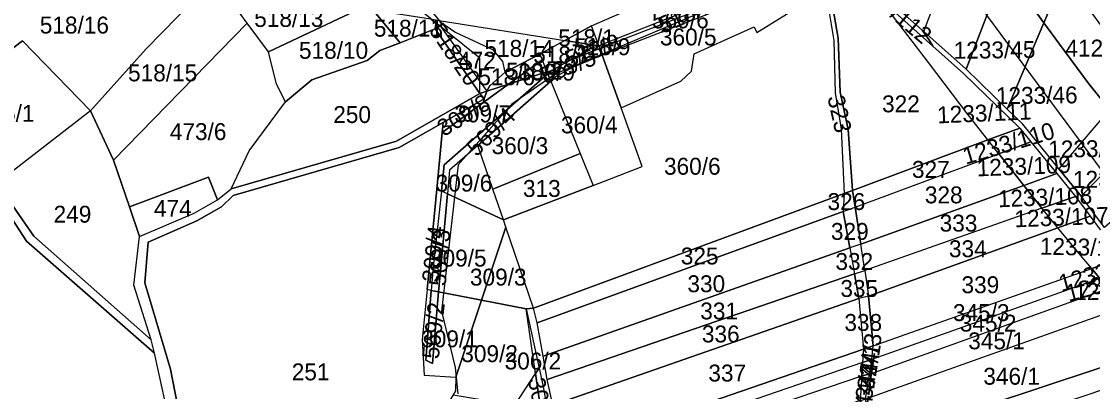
# Model space of a CAD drawing. Extents: x -623250 to -619626, y -1079612 to -1075424.
# Drawn here: x -621523 to -620889, y -1076399 to -1076180 of the extents above; entities that cross this region are included whole.
import ezdxf

# ---------------------------------------------------------------- set-up
doc = ezdxf.new("R2010")
doc.units = 0
for name, color, linetype in [('Cestní síť', 7, 'Continuous'), ('Dálnice a přivaděč', 7, 'Continuous'), ('Hranice převzatá (k_ú_Džbánov - vnitřní obvod)', 7, 'Continuous'), ('Hranice šetřená (k_ú_Džbánov - vnitřní obvod)', 7, 'Continuous'), ('Parcela nároku', 7, 'Continuous'), ('Parcelní číslo', 7, 'Continuous'), ('Vodní toky', 7, 'Continuous')]:
    doc.layers.add(name, color=color, linetype=linetype)

msp = doc.modelspace()

# ---------------------------------------------------------------- linework, layer by layer
at = {"layer": 'Cestní síť'}
for p, q in [((-621251.46, -1076201.51), (-621289.81, -1076170.77)), ((-621251.46, -1076222.32), (-621251.46, -1076201.51))]:
    msp.add_line(p, q, dxfattribs=at)
at = {"layer": 'Dálnice a přivaděč'}
msp.add_lwpolyline([(-621211.3, -1075762.42), (-621042.48, -1076053.84), (-620715.11, -1076495.7), (-620421.91, -1076809.46), (-620180.94, -1077181.74)], dxfattribs=at)
at = {"layer": 'Hranice převzatá (k_ú_Džbánov - vnitřní obvod)'}
msp.add_line((-621579.54, -1076234.75), (-621521.93, -1076191.24), dxfattribs=at)
at = {"layer": 'Hranice šetřená (k_ú_Džbánov - vnitřní obvod)'}
msp.add_line((-621521.93, -1076191.24), (-621481.81, -1076232.64), dxfattribs=at)
for points in [[(-621398.6, -1076278.8), (-621387.93, -1076256.33), (-621366.5, -1076227.36), (-621350.88, -1076214.35), (-621318.15, -1076202.75), (-621310.65, -1076196.95), (-621298.69, -1076192.28), (-621277.92, -1076184.17), (-621251.46, -1076222.32), (-621248.98, -1076225.48)], [(-621248.98, -1076225.48), (-621273.17, -1076239.48), (-621273.74, -1076245.43), (-621276.97, -1076278.86), (-621282.72, -1076338.34), (-621285.57, -1076367.86), (-621284.5, -1076389.01), (-621265.66, -1076390.24), (-621265.87, -1076398.19), (-621267.29, -1076400.57), (-621287.59, -1076434.78)], [(-621481.81, -1076232.64), (-621468.08, -1076261.86), (-621458.77, -1076289.32), (-621452.8, -1076306.94)], [(-621452.8, -1076306.94), (-621420.38, -1076293.14), (-621406.58, -1076285.18), (-621398.6, -1076278.8)]]:
    msp.add_lwpolyline(points, dxfattribs=at)
at = {"layer": 'Parcela nároku'}
for points in [[(-621115.64, -1076136.14), (-621117.67, -1076134.09), (-621106.64, -1076105.12), (-621112.1, -1076099.11), (-621115.06, -1076094.93), (-621125.96, -1076121.85), (-621133.54, -1076112.69), (-621138.97, -1076106.12), (-621291.08, -1076154.04), (-621287.17, -1076164.84), (-621275.63, -1076179.09), (-621201.26, -1076190.91), (-621185.47, -1076182.33), (-621164.23, -1076173.07), (-621116.59, -1076154.34)], [(-621608.24, -1076210.58), (-621629.35, -1076180.25), (-621633.46, -1076172.64), (-621671.01, -1076103.12), (-621673.69, -1076105.55), (-621673.97, -1076108.64), (-621630.46, -1076185.6), (-621609.84, -1076214.68), (-621593.16, -1076232.82), (-621559.82, -1076255.99), (-621548.19, -1076267.39), (-621534.67, -1076286.18), (-621519.6, -1076309.69), (-621443.92, -1076376.02), (-621445.95, -1076368.04), (-621515.23, -1076306.72), (-621537.06, -1076275.42), (-621545.36, -1076263.71), (-621552.94, -1076255.31), (-621556.59, -1076252.07), (-621565.07, -1076245.21), (-621579.54, -1076234.75), (-621591.29, -1076229.48)], [(-620981.03, -1076125.68), (-621000.13, -1076175.93), (-620990.09, -1076184.83), (-620989.05, -1076185.75), (-620962.72, -1076115.61), (-620972.17, -1076100.76)], [(-620962.72, -1076115.61), (-620945.72, -1076141.84), (-620941.1, -1076148.36), (-620964.04, -1076207.93), (-620989.05, -1076185.75)], [(-621116.59, -1076154.34), (-621115.64, -1076136.14), (-621088.15, -1076132.5), (-621088.62, -1076135.84), (-621091.79, -1076143.34), (-621096.62, -1076149.38), (-621100.38, -1076152.42), (-621105.1, -1076155), (-621103.02, -1076163.08), (-621181.25, -1076194.09), (-621185.47, -1076182.33), (-621164.23, -1076173.07)], [(-620983.64, -1076194.27), (-620986.12, -1076190.38), (-620990.09, -1076184.83), (-621000.13, -1076175.93), (-621010.03, -1076167.16), (-621020.59, -1076157.79), (-621025.94, -1076153.05), (-621029.28, -1076149.52), (-621045.76, -1076132.11), (-621046.36, -1076134.95), (-621043.64, -1076137.84), (-621036.2, -1076145.74), (-621027.6, -1076154.87), (-621015.19, -1076165.99)], [(-621545.21, -1076174.84), (-621511.86, -1076137.39), (-621411.38, -1076157.52), (-621448.91, -1076195.83), (-621481.81, -1076232.64), (-621521.93, -1076191.24), (-621579.54, -1076234.75), (-621591.29, -1076229.48), (-621571.76, -1076206.32)], [(-621184.57, -1076276.71), (-621155.58, -1076265.61), (-621168.04, -1076230.88), (-621132.79, -1076214.96), (-621126.36, -1076209.09), (-621124.87, -1076198.94), (-621089.4, -1076182.83), (-621087.81, -1076186.18), (-621063.52, -1076171.28), (-621067.09, -1076159.01), (-621062.29, -1076156.68), (-621053.44, -1076148.59), (-621047.26, -1076139.56), (-621046.46, -1076140.01), (-621046.9, -1076162.42), (-621042.18, -1076191.09), (-621041.44, -1076221.89), (-621037.97, -1076243.36), (-621036.14, -1076281.57), (-621219.72, -1076349.42), (-621236.11, -1076301.49), (-621237.65, -1076297.02)], [(-621043.75, -1076141.52), (-621046.46, -1076140.01), (-621046.9, -1076162.42), (-621042.18, -1076191.09), (-621041.44, -1076221.89), (-621037.97, -1076243.36), (-621036.14, -1076281.57), (-621031.17, -1076279.7), (-621033.73, -1076243.61), (-621038.59, -1076221.47), (-621039.62, -1076189.6), (-621044.35, -1076162.21)], [(-620951.18, -1076249.84), (-620962.76, -1076235.06), (-620986.33, -1076204.09), (-621015.19, -1076165.99), (-621027.6, -1076154.87), (-621036.2, -1076145.74), (-621043.75, -1076141.52), (-621044.35, -1076162.21), (-621039.62, -1076189.6), (-621038.59, -1076221.47), (-621033.73, -1076243.61), (-621031.17, -1076279.7)], [(-620936.62, -1076136.73), (-620906.01, -1076152.15), (-620918.03, -1076180.48), (-620928.01, -1076166.82), (-620941.1, -1076148.36)], [(-620964.04, -1076207.93), (-620941.1, -1076148.36), (-620928.01, -1076166.82), (-620918.03, -1076180.48), (-620939.7, -1076231.54)], [(-620906.01, -1076152.15), (-620862.49, -1076212.3), (-620879.21, -1076231.86), (-620891.48, -1076216.57), (-620908.73, -1076193.21), (-620918.03, -1076180.48)], [(-621389.09, -1076180.71), (-621392.88, -1076175.55), (-621405.44, -1076158.46), (-621411.38, -1076157.52), (-621448.91, -1076195.83), (-621481.81, -1076232.64), (-621468.08, -1076261.86)], [(-621384.78, -1076161.74), (-621321.63, -1076171.78), (-621376.56, -1076197.76), (-621389.09, -1076180.71), (-621392.88, -1076175.55)], [(-621100.8, -1076169.23), (-621179.22, -1076199.74), (-621168.04, -1076230.88), (-621132.79, -1076214.96), (-621126.36, -1076209.09), (-621124.87, -1076198.94), (-621089.4, -1076182.83), (-621087.81, -1076186.18), (-621063.52, -1076171.28), (-621067.09, -1076159.01), (-621086.5, -1076168.47), (-621097.9, -1076174.53)], [(-621102.49, -1076165.14), (-621103.02, -1076163.08), (-621181.25, -1076194.09), (-621177.95, -1076194.61)], [(-621180.68, -1076195.68), (-621177.95, -1076194.61), (-621102.49, -1076165.14), (-621100.8, -1076169.23), (-621179.22, -1076199.74)], [(-620983.64, -1076194.27), (-620965.61, -1076210.43), (-620932.35, -1076242.81), (-620951.18, -1076249.84), (-620962.76, -1076235.06), (-620986.33, -1076204.09), (-621015.19, -1076165.99)], [(-621314.75, -1076172.87), (-621298.69, -1076192.28), (-621310.65, -1076196.95), (-621318.15, -1076202.75), (-621350.88, -1076214.35), (-621366.5, -1076227.36), (-621371.7, -1076216.84), (-621376.56, -1076197.76), (-621321.63, -1076171.78)], [(-621314.75, -1076172.87), (-621280.8, -1076178.27), (-621277.59, -1076181.22), (-621277.92, -1076184.17), (-621298.69, -1076192.28)], [(-621376.56, -1076197.76), (-621389.09, -1076180.71), (-621468.08, -1076261.86), (-621458.77, -1076289.32), (-621412.06, -1076271.81), (-621406.58, -1076285.18), (-621398.6, -1076278.8), (-621387.93, -1076256.33), (-621366.5, -1076227.36), (-621371.7, -1076216.84)], [(-621274.68, -1076180.26), (-621274.5, -1076183.18), (-621247.35, -1076220.98), (-621251.46, -1076222.32), (-621277.92, -1076184.17), (-621277.59, -1076181.22), (-621280.8, -1076178.27), (-621275.63, -1076179.09)], [(-621275.63, -1076179.09), (-621201.26, -1076190.91), (-621216.16, -1076199.01), (-621236.49, -1076209.65), (-621237.87, -1076203.47), (-621243.4, -1076196.62), (-621266.41, -1076186.05), (-621274.68, -1076180.26)], [(-621236.49, -1076209.65), (-621237.87, -1076203.47), (-621243.4, -1076196.62), (-621266.41, -1076186.05), (-621274.68, -1076180.26), (-621274.5, -1076183.18), (-621247.35, -1076220.98), (-621245.49, -1076217.63)], [(-620918.03, -1076180.48), (-620908.73, -1076193.21), (-620891.48, -1076216.57), (-620879.21, -1076231.86), (-620909.12, -1076266.84), (-620930.47, -1076240.49), (-620939.7, -1076231.54)], [(-621398.6, -1076278.8), (-621387.93, -1076256.33), (-621366.5, -1076227.36), (-621350.88, -1076214.35), (-621318.15, -1076202.75), (-621310.65, -1076196.95), (-621298.69, -1076192.28), (-621277.92, -1076184.17), (-621251.46, -1076222.32), (-621300.88, -1076250.62)], [(-621181.25, -1076194.09), (-621185.47, -1076182.33), (-621201.26, -1076190.91)], [(-621579.54, -1076234.75), (-621521.93, -1076191.24), (-621481.81, -1076232.64), (-621537.06, -1076275.42), (-621545.36, -1076263.71), (-621552.94, -1076255.31), (-621556.59, -1076252.07), (-621565.07, -1076245.21)], [(-621201.26, -1076190.91), (-621216.16, -1076199.01), (-621214.79, -1076202.37), (-621211.9, -1076209.47), (-621208.78, -1076208.46), (-621198.57, -1076202.83), (-621186.07, -1076195.62), (-621181.25, -1076194.09)], [(-621247.35, -1076220.98), (-621245.49, -1076217.63), (-621236.49, -1076209.65), (-621216.16, -1076199.01), (-621214.79, -1076202.37), (-621234.61, -1076216.84)], [(-621185.32, -1076197.49), (-621180.68, -1076195.68), (-621179.22, -1076199.74), (-621183.92, -1076201.57), (-621196.4, -1076206.77), (-621206.39, -1076212.29), (-621209.61, -1076215.12), (-621211.38, -1076210.75), (-621208.78, -1076208.46), (-621198.57, -1076202.83)], [(-621155.58, -1076265.61), (-621168.04, -1076230.88), (-621179.22, -1076199.74), (-621183.92, -1076201.57), (-621196.4, -1076206.77), (-621206.39, -1076212.29), (-621209.61, -1076215.12), (-621192.25, -1076257.82), (-621184.57, -1076276.71)], [(-621198.57, -1076202.83), (-621186.07, -1076195.62), (-621181.25, -1076194.09), (-621180.68, -1076195.68), (-621185.32, -1076197.49)], [(-621181.25, -1076194.09), (-621177.95, -1076194.61), (-621180.68, -1076195.68)], [(-621214.79, -1076202.37), (-621211.9, -1076209.47), (-621234.61, -1076216.84)], [(-621273.74, -1076245.43), (-621234.61, -1076216.84), (-621211.9, -1076209.47), (-621211.38, -1076210.75), (-621272.57, -1076264.53), (-621274.27, -1076280.11), (-621276.97, -1076278.86)], [(-621272.57, -1076264.53), (-621211.38, -1076210.75), (-621209.61, -1076215.12), (-621252.79, -1076253.14), (-621269.4, -1076267.61), (-621270.69, -1076281.77), (-621274.27, -1076280.11)], [(-621211.9, -1076209.47), (-621208.78, -1076208.46), (-621211.38, -1076210.75)], [(-621248.98, -1076225.48), (-621247.35, -1076220.98), (-621234.61, -1076216.84), (-621273.74, -1076245.43), (-621273.17, -1076239.48)], [(-621252.79, -1076253.14), (-621209.61, -1076215.12), (-621192.25, -1076257.82), (-621243.87, -1076278.99)], [(-621468.08, -1076261.86), (-621481.81, -1076232.64), (-621537.06, -1076275.42), (-621515.23, -1076306.72), (-621445.95, -1076368.04), (-621456.14, -1076335.71), (-621452.8, -1076306.94), (-621458.77, -1076289.32)], [(-620879.21, -1076231.86), (-620909.12, -1076266.84), (-620896, -1076283.02), (-620863.74, -1076249.9), (-620872.76, -1076239.91)], [(-620932.35, -1076242.81), (-620925.69, -1076251), (-620944.74, -1076258.07), (-620951.18, -1076249.84)], [(-620944.74, -1076258.07), (-620951.18, -1076249.84), (-621031.17, -1076279.7), (-621029.68, -1076289.57)], [(-620863.74, -1076249.9), (-620855.36, -1076259.18), (-620845.7, -1076268.87), (-620879.11, -1076298.89), (-620882.2, -1076301.66), (-620896, -1076283.02)], [(-621243.87, -1076278.99), (-621252.79, -1076253.14), (-621269.4, -1076267.61), (-621270.69, -1076281.77), (-621237.65, -1076297.02)], [(-620944.74, -1076258.07), (-620925.69, -1076251), (-620910.45, -1076269.73), (-620929.96, -1076276.75), (-620936.5, -1076268.58)], [(-621243.87, -1076278.99), (-621192.25, -1076257.82), (-621184.57, -1076276.71), (-621237.65, -1076297.02)], [(-621029.68, -1076289.57), (-620944.74, -1076258.07), (-620936.5, -1076268.58), (-620929.96, -1076276.75), (-621026.37, -1076311.45)], [(-621406.58, -1076285.18), (-621412.06, -1076271.81), (-621458.77, -1076289.32), (-621452.8, -1076306.94), (-621420.38, -1076293.14)], [(-620929.96, -1076276.75), (-620910.45, -1076269.73), (-620899.46, -1076283.25), (-620919.19, -1076290.18)], [(-621282.72, -1076338.34), (-621276.97, -1076278.86), (-621274.27, -1076280.11), (-621279.16, -1076324.82), (-621280.24, -1076338.82)], [(-621270.69, -1076281.77), (-621274.27, -1076280.11), (-621279.16, -1076324.82), (-621280.24, -1076338.82), (-621275.9, -1076339.67), (-621274.64, -1076325.25)], [(-621274.64, -1076325.25), (-621275.9, -1076339.67), (-621250.47, -1076344.63), (-621236.11, -1076301.49), (-621237.65, -1076297.02), (-621270.69, -1076281.77)], [(-621219.72, -1076349.42), (-621036.14, -1076281.57), (-621036.71, -1076292.18), (-621217.58, -1076357.97)], [(-621036.14, -1076281.57), (-621036.71, -1076292.18), (-621029.68, -1076289.57), (-621031.17, -1076279.7)], [(-621026.37, -1076311.45), (-620929.96, -1076276.75), (-620919.19, -1076290.18), (-621024.01, -1076327.01)], [(-620899.46, -1076283.25), (-620890.78, -1076294.93), (-620909.76, -1076301.79), (-620913.91, -1076296.76), (-620919.19, -1076290.18)], [(-621217.58, -1076357.97), (-621036.71, -1076292.18), (-621032.84, -1076313.74), (-621214.08, -1076377.82)], [(-621036.71, -1076292.18), (-621029.68, -1076289.57), (-621026.37, -1076311.45), (-621032.84, -1076313.74)], [(-620909.76, -1076301.79), (-620913.91, -1076296.76), (-620919.19, -1076290.18), (-621024.01, -1076327.01), (-621021.7, -1076342.29)], [(-620884.55, -1076303.3), (-620873.36, -1076320.14), (-620889.79, -1076325.94), (-620894.38, -1076320.42), (-620909.76, -1076301.79), (-620890.78, -1076294.93)], [(-621219.72, -1076349.42), (-621236.11, -1076301.49), (-621250.47, -1076344.63), (-621224.07, -1076349.79)], [(-620894.38, -1076320.42), (-620909.76, -1076301.79), (-621021.7, -1076342.29), (-621019.01, -1076371.58), (-620889.79, -1076325.94)], [(-621032.84, -1076313.74), (-621030.08, -1076329.13), (-621211.65, -1076391.56), (-621214.08, -1076377.82)], [(-621024.01, -1076327.01), (-621026.37, -1076311.45), (-621032.84, -1076313.74), (-621030.08, -1076329.13)], [(-621019.78, -1076379.78), (-621019.01, -1076371.58), (-620889.79, -1076325.94), (-620884.98, -1076331.71)], [(-620889.79, -1076325.94), (-620873.36, -1076320.14), (-620868.82, -1076325.95), (-620884.98, -1076331.71)], [(-621030.08, -1076329.13), (-621027.46, -1076343.71), (-621208.34, -1076406.79), (-621211.65, -1076391.56)], [(-621030.08, -1076329.13), (-621024.01, -1076327.01), (-621021.7, -1076342.29), (-621027.46, -1076343.71)], [(-620879.98, -1076337.73), (-620884.98, -1076331.71), (-621019.78, -1076379.78), (-621020.46, -1076384.11), (-621021.13, -1076388.31)], [(-621250.47, -1076344.63), (-621275.9, -1076339.67), (-621279.61, -1076382.04), (-621283.44, -1076380.1), (-621280.24, -1076338.82), (-621282.72, -1076338.34), (-621285.57, -1076367.86), (-621284.5, -1076389.01), (-621265.66, -1076390.24)], [(-621275.9, -1076339.67), (-621280.24, -1076338.82), (-621283.44, -1076380.1), (-621279.61, -1076382.04)], [(-621021.13, -1076388.31), (-620879.98, -1076337.73), (-620870.74, -1076348.82), (-621023.49, -1076403.2)], [(-621224.07, -1076349.79), (-621250.47, -1076344.63), (-621265.66, -1076390.24), (-621265.87, -1076398.19), (-621267.29, -1076400.57), (-621230.78, -1076406.79), (-621218.56, -1076387.98)], [(-621208.34, -1076406.79), (-621027.46, -1076343.71), (-621024.8, -1076373.62), (-621199.34, -1076433.72), (-621204.93, -1076422.43)], [(-621019.01, -1076371.58), (-621021.7, -1076342.29), (-621027.46, -1076343.71), (-621024.8, -1076373.62)], [(-621208.34, -1076406.79), (-621211.65, -1076391.56), (-621214.08, -1076377.82), (-621217.58, -1076357.97), (-621219.72, -1076349.42), (-621224.07, -1076349.79), (-621216.51, -1076384.81), (-621214.33, -1076394.9), (-621209.35, -1076420.98), (-621154.18, -1076534.12), (-621073.3, -1076707.13), (-621070.3, -1076705.45), (-621118.59, -1076599.86), (-621139.26, -1076556.24), (-621151.08, -1076531.28), (-621162.18, -1076508.84), (-621168.39, -1076496.29), (-621174.76, -1076483.41), (-621186.59, -1076459.5), (-621193.11, -1076446.32), (-621196.12, -1076440.23), (-621199.34, -1076433.72), (-621204.93, -1076422.43)], [(-621224.07, -1076349.79), (-621216.51, -1076384.81), (-621218.56, -1076387.98)], [(-620856.46, -1076365.89), (-620870.74, -1076348.82), (-621023.49, -1076403.2), (-621021.51, -1076429.95), (-620850.81, -1076373.39)], [(-621199.34, -1076433.72), (-621024.8, -1076373.62), (-621025.39, -1076381.44), (-621196.12, -1076440.23)], [(-621024.8, -1076373.62), (-621025.39, -1076381.44), (-621019.78, -1076379.78), (-621019.01, -1076371.58)], [(-620845.66, -1076381.41), (-620850.81, -1076373.39), (-621021.51, -1076429.95), (-621020.47, -1076443.97), (-620844.2, -1076384.27)], [(-621025.39, -1076381.44), (-621196.12, -1076440.23), (-621193.11, -1076446.32), (-621025.72, -1076389.45)], [(-621025.39, -1076381.44), (-621025.72, -1076389.45), (-621021.13, -1076388.31), (-621020.46, -1076384.11), (-621019.78, -1076379.78)], [(-621230.78, -1076406.79), (-621218.56, -1076387.98), (-621213.66, -1076421.95), (-621209.35, -1076420.98), (-621154.18, -1076534.12), (-621073.3, -1076707.13), (-621076.55, -1076708.96), (-621098.91, -1076722.13), (-621152.55, -1076609.83), (-621197.51, -1076520.1), (-621242.51, -1076430.2), (-621244, -1076427.14)], [(-621214.33, -1076394.9), (-621209.35, -1076420.98), (-621213.66, -1076421.95), (-621218.56, -1076387.98), (-621216.51, -1076384.81)], [(-621193.11, -1076446.32), (-621025.72, -1076389.45), (-621026.74, -1076403.96), (-621186.59, -1076459.5)], [(-621021.13, -1076388.31), (-621025.72, -1076389.45), (-621026.74, -1076403.96), (-621023.49, -1076403.2)]]:
    msp.add_lwpolyline(points, close=True, dxfattribs=at)
for points in [[(-621433.49, -1076423.69), (-621443.92, -1076376.02), (-621519.6, -1076309.69), (-621534.67, -1076286.18), (-621548.19, -1076267.39), (-621559.82, -1076255.99), (-621593.16, -1076232.82), (-621609.84, -1076214.68), (-621630.46, -1076185.6), (-621673.97, -1076108.64), (-621680.23, -1076106.84), (-621724.41, -1076112.53), (-621740.51, -1076116.66), (-621794.41, -1076142.67), (-621819.7, -1076148.36), (-621849.17, -1076151.4), (-621870.23, -1076151.84), (-621887.97, -1076151.54), (-621911.39, -1076149.25), (-621914.42, -1076147.38), (-621949.27, -1076155.42), (-621983.55, -1076172.97), (-622004.66, -1076190.4), (-622057.42, -1076239.51)], [(-620882.2, -1076301.66), (-620896, -1076283.02), (-620909.12, -1076266.84), (-620930.47, -1076240.49), (-620939.7, -1076231.54), (-620964.04, -1076207.93), (-620989.05, -1076185.75), (-620990.09, -1076184.83), (-620986.12, -1076190.38), (-620983.64, -1076194.27), (-620965.61, -1076210.43), (-620932.35, -1076242.81), (-620925.69, -1076251), (-620910.45, -1076269.73), (-620899.46, -1076283.25), (-620890.78, -1076294.93), (-620884.55, -1076303.3)], [(-621433.49, -1076423.69), (-621443.92, -1076376.02), (-621445.95, -1076368.04), (-621456.14, -1076335.71), (-621452.8, -1076306.94), (-621420.38, -1076293.14), (-621406.58, -1076285.18), (-621398.6, -1076278.8), (-621300.88, -1076250.62), (-621251.46, -1076222.32), (-621247.35, -1076220.98), (-621248.98, -1076225.48), (-621273.17, -1076239.48), (-621299.31, -1076254.26), (-621397.34, -1076282.77), (-621404.21, -1076289.3), (-621418.81, -1076297.64), (-621447.6, -1076310.3), (-621449.62, -1076334.39), (-621434.41, -1076385.42), (-621427.83, -1076419.86)], [(-621427.83, -1076419.86), (-621434.41, -1076385.42), (-621449.62, -1076334.39), (-621447.6, -1076310.3), (-621418.81, -1076297.64), (-621404.21, -1076289.3), (-621397.34, -1076282.77), (-621299.31, -1076254.26), (-621273.17, -1076239.48), (-621273.74, -1076245.43), (-621276.97, -1076278.86), (-621282.72, -1076338.34), (-621285.57, -1076367.86), (-621284.5, -1076389.01), (-621265.66, -1076390.24), (-621265.87, -1076398.19), (-621267.29, -1076400.57)]]:
    msp.add_lwpolyline(points, dxfattribs=at)
at = {"layer": 'Vodní toky'}
for p, q in [((-621079.45, -1076156.83), (-621207.02, -1076210.89)), ((-621207.02, -1076210.89), (-621232.54, -1076228.6)), ((-621232.54, -1076228.6), (-621264.3, -1076264.55)), ((-621264.3, -1076264.55), (-621274.19, -1076351.04)), ((-621274.19, -1076351.04), (-621266.08, -1076384.38)), ((-621266.08, -1076384.38), (-621264.5, -1076400))]:
    msp.add_line(p, q, dxfattribs=at)

# ---------------------------------------------------------------- texts
at = {"layer": 'Parcelní číslo'}
for s, rotation, p in [('1233/112', 319.48128, (-621032.17, -1076157.47)), ('518/41', 24.91803, (-621143.2, -1076187.23)), ('518/20', 304.24905, (-621281.94, -1076185.14)), ('518/8', 19.38456, (-621199.11, -1076207.15)), ('1233/45', 0.57294, (-620971.35, -1076201.8)), ('569/5', 20.90592, (-621213.09, -1076216.87)), ('1233/46', 0.57294, (-620946.4, -1076228.64)), ('309/8', 31.45095, (-621272.85, -1076248.15)), ('323', 282.44241, (-621046.09, -1076224.53)), ('569/4', 44.37216, (-621253.5, -1076260.16)), ('1233/111', 2.46375, (-620980.95, -1076240.07)), ('1233/110', 16.50114, (-620964.28, -1076264.5)), ('1233/47', 0.57294, (-620915.46, -1076260.25)), ('1233/109', 2.23452, (-620957.56, -1076271.41)), ('1233/48', 0.57294, (-620900.82, -1076278.21)), ('1233/108', 2.23452, (-620945.06, -1076289.69)), ('1233/107', 2.23452, (-620935.25, -1076301.55)), ('309/4', 83.55744, (-621275.89, -1076334.44)), ('569/3', 85.23639, (-621271.73, -1076336.55)), ('1233/106', 358.8435, (-620920.5, -1076317.65)), ('1233/105', 14.61042, (-620907.77, -1076339.68)), ('1233/104', 14.61042, (-620903.48, -1076345.62)), ('1233/103', 0.40104, (-620900.09, -1076344.59)), ('569/2', 83.76435, (-621275.85, -1076379.78)), ('344/3', 81.49077, (-621018.74, -1076398.1)), ('344/1', 80.57484, (-621019.86, -1076404.05)), ('344/2', 81.5796, (-621021.18, -1076416.03)), ('306/1', 281.52261, (-621223.18, -1076391.44))]:
    msp.add_text(s, height=10, rotation=rotation, dxfattribs=at).set_placement(p)
for s, p in [('518/13', (-621384.94, -1076182.97)), ('569/6', (-621149.7, -1076183.8)), ('518/16', (-621511.73, -1076186.87)), ('518/11', (-621314.2, -1076188.72)), ('518/1', (-621205.18, -1076194.4)), ('360/5', (-621145.05, -1076193.9)), ('518/10', (-621358.49, -1076201.82)), ('518/14', (-621248.81, -1076200.67)), ('518/9', (-621195.95, -1076199.71)), ('412', (-620905.32, -1076200.48)), ('472', (-621264.41, -1076207.66)), ('518/7', (-621219.99, -1076204.33)), ('518/15', (-621459.52, -1076215.14)), ('518/2', (-621236.07, -1076214.18)), ('309/9', (-621228.7, -1076214.72)), ('518/6', (-621252.42, -1076217.46)), ('322', (-621013.73, -1076233.47)), ('475/1', (-621548.3, -1076239.09)), ('250', (-621338.21, -1076239.8)), ('309/7', (-621266.61, -1076239.43)), ('360/4', (-621203.58, -1076245.92)), ('473/6', (-621434.83, -1076249.9)), ('360/3', (-621244.58, -1076258.21)), ('360/6', (-621142.65, -1076270.4)), ('327', (-620996.04, -1076272.26)), ('309/6', (-621277.66, -1076280.38)), ('313', (-621226.06, -1076283.52)), ('326', (-621045.96, -1076291.29)), ('328', (-620988.43, -1076287.33)), ('474', (-621444.22, -1076295.31)), ('249', (-621503.55, -1076298.76)), ('333', (-620979.69, -1076304.04)), ('329', (-621043.95, -1076308.94)), ('325', (-621132.73, -1076323.49)), ('334', (-620974.19, -1076319.2)), ('309/5', (-621281.03, -1076324.72)), ('332', (-621041.29, -1076326.74)), ('309/3', (-621257.4, -1076335.98)), ('330', (-621128.82, -1076339.91)), ('335', (-621038.37, -1076342.7)), ('339', (-620966.76, -1076340.49)), ('331', (-621121.22, -1076356.01)), ('345/3', (-620971.85, -1076356.97)), ('338', (-621036.01, -1076362.81)), ('345/2', (-620967.77, -1076363.21)), ('309/1', (-621286.21, -1076372.49)), ('336', (-621120.26, -1076369.62)), ('345/1', (-620962.77, -1076373.68)), ('309/2', (-621262.5, -1076381.27)), ('306/2', (-621236.89, -1076385.61)), ('251', (-621362.75, -1076392.04)), ('337', (-621116.42, -1076392.73)), ('346/1', (-620953.85, -1076394.62))]:
    msp.add_text(s, height=10, dxfattribs=at).set_placement(p)

doc.saveas('drawing.dxf')
